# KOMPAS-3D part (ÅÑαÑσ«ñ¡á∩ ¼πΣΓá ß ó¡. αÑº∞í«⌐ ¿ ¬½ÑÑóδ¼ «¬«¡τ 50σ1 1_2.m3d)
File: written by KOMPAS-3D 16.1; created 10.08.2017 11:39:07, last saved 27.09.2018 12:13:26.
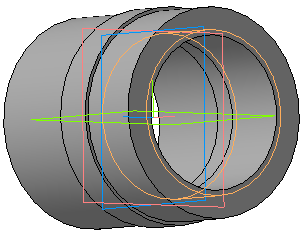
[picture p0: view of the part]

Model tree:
1. Эскиз:1
2. Операция вращения:1
     Угол 1 = 360
3. Условное изображение резьбы:2
     Длина резьбы = 21.4; Шаг резьбы = 2.309; Номинальный диаметр резьбы = 47.803
4. Подгонка:1

Expressions: v463+4; G 1.1/2
Referenced files in C:\Program Files\ASCON\KOMPAS-3D V16\Sys\Thread\: cil2_6357-81.xml
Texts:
  Линейный размер с обрывом
  Переходная муфта с вн. резьбой и клеевым оконч с др. стороны 50х1 1_2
